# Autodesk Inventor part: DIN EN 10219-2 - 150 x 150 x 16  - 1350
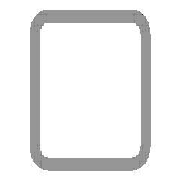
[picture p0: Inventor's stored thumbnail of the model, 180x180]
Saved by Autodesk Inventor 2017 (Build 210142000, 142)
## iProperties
_CCFamilyMember: 76
_CCFamilyDisplayName: DIN EN 10219-2 (Square Hollow Section - Cold Formed) - Cold formed welded structural hollow sections of non-alloy and fine grain structural steel
_FrameMemberDoc: Frame Member File
_Version: 15.0.0
_GetPNFromCC: 1
Created: 2017-11
Part Number: DIN EN 10219-2 - 150 x 150 x 16  - 1350
Material: Steel, Mild
Description: Cold formed welded structural hollow sections of non-alloy and fine grain structural steel
Document SubType Name: Modeling
Standard: DIN
Designer: iusti
Standard Revision: 2006-07
Standards Organization: DIN
Language: en-US
Size Designation: 150 x 150 x 16
Categories: <MemberInstance><Categories><Category DisplayName="Structural Shapes" InternalName="089c4875-fa83-4c05-b084-43b9cc11f5ed" Mnemonic="GRDR"><CategoryParameter Dis
Stock Number: 150 x 150 x 16
Mass: 79240 g
Surface Area: 12767.4 cm^2
Volume: 10094.3 cm^3
Density: 7.85 g/cm^3
Appearance: Semi-Polished
IsCustomPart: 1
G_L: 1350.000 mm
G_W: 150.000 mm
G_H: 150.000 mm
+1055AC61-50C7-4DA5-AE5C-F84627A246C8+CUTDETAIL1: Cut
+221E46B8-E6FF-404F-B431-F4B8D67D182E+CUTDETAIL2: Cut
Author: iusti
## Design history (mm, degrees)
node "Start plane"
node "End plane"
sketch "Sketch"
  geometry: L1 (-75, -27)-(-75, 27); L2 (-27, 75)-(27, 75); L3 (75, 27)-(75, -27); L4 (27, -75)-(-27, -75); L5 (-27, 59)-(27, 59); L6 (59, 27)-(59, -27); L7 (27, -59)-(-27, -59); L8 (-59, -27)-(-59, 27); L9 (0, 118.918)-(0, -118.918) reference; L10 (-118.918, 0)-(118.918, 0) reference; A1 r 48 centre (-27, -27) between (-75, -27) and (-27, -75); A2 r 48 centre (-27, 27) between (-27, 75) and (-75, 27); A3 r 48 centre (27, 27) between (75, 27) and (27, 75); A4 r 48 centre (27, -27) between (27, -75) and (75, -27); A5 r 32 centre (-27, 27) between (-27, 59) and (-59, 27); A6 r 32 centre (27, 27) between (59, 27) and (27, 59); A7 r 32 centre (27, -27) between (27, -59) and (59, -27); A8 r 32 centre (-27, -27) between (-59, -27) and (-27, -59)
  constraints: 16 end point, 16 point on circle, 8 centre point, 8 tangent, 4 parallel, 3 equal radius, 2 perpendicular, 7 other
  dimensions: "d7" = 48 radius of A1 (= G_IR); "d10" = 150 distance between parallel lines of L2 L4 (= G_H); "d11" = 150 distance between parallel lines of L1 L3 (= G_W); "d12" = 16 distance between parallel lines of L3 L6 (= G_T); "d15" = 75 distance between parallel lines of L2 L10 (= 0.5 x d10); "d16" = 75 distance between parallel lines of L9 L3 (= 0.5 x d11)
extrude "Body" new body sketch "Sketch" stored distance "d3" = 1350 (= G_L); taper "d4" = 0 deg
node "Driven Length"
  sketch "Sketch3"
    geometry: L1 (0, 0)-(10, 0) reference
    constraints: 2 end point, 1 horizontal
  workplane "Work Plane3"
  sketch "Sketch4"
    geometry: L1 (-2, 75)-(12, 75) reference; L2 (-2, 1425)-(12, 1425) reference
    dimensions: "d18" = 1350 distance between parallel lines of L1 L2 (derived)
workplane "Work Plane4"
split "Split1"
workplane "Work Plane5"
split "Split2"
body "Solid1"
other parameters: "G_W" = 150 [user parameter; used in 1 equation term], "G_H" = 150 [user parameter; used in 1 equation term], "G_T" = 16 [user parameter; used in 1 equation term], "G_IR" = 48 [user parameter; used in 1 equation term], "G_L" = 1350 (= d18) [user parameter; used in 1 equation term], "G_OFFSET_START" = -75 [user parameter; used in 1 equation term], "G_OFFSET_END" = -75 [user parameter; used in 1 equation term], "d13" = 75 (= -G_OFFSET_START), "d14" = 1425 (= G_OFFSET_END + B_L), "d17" = 90 deg
